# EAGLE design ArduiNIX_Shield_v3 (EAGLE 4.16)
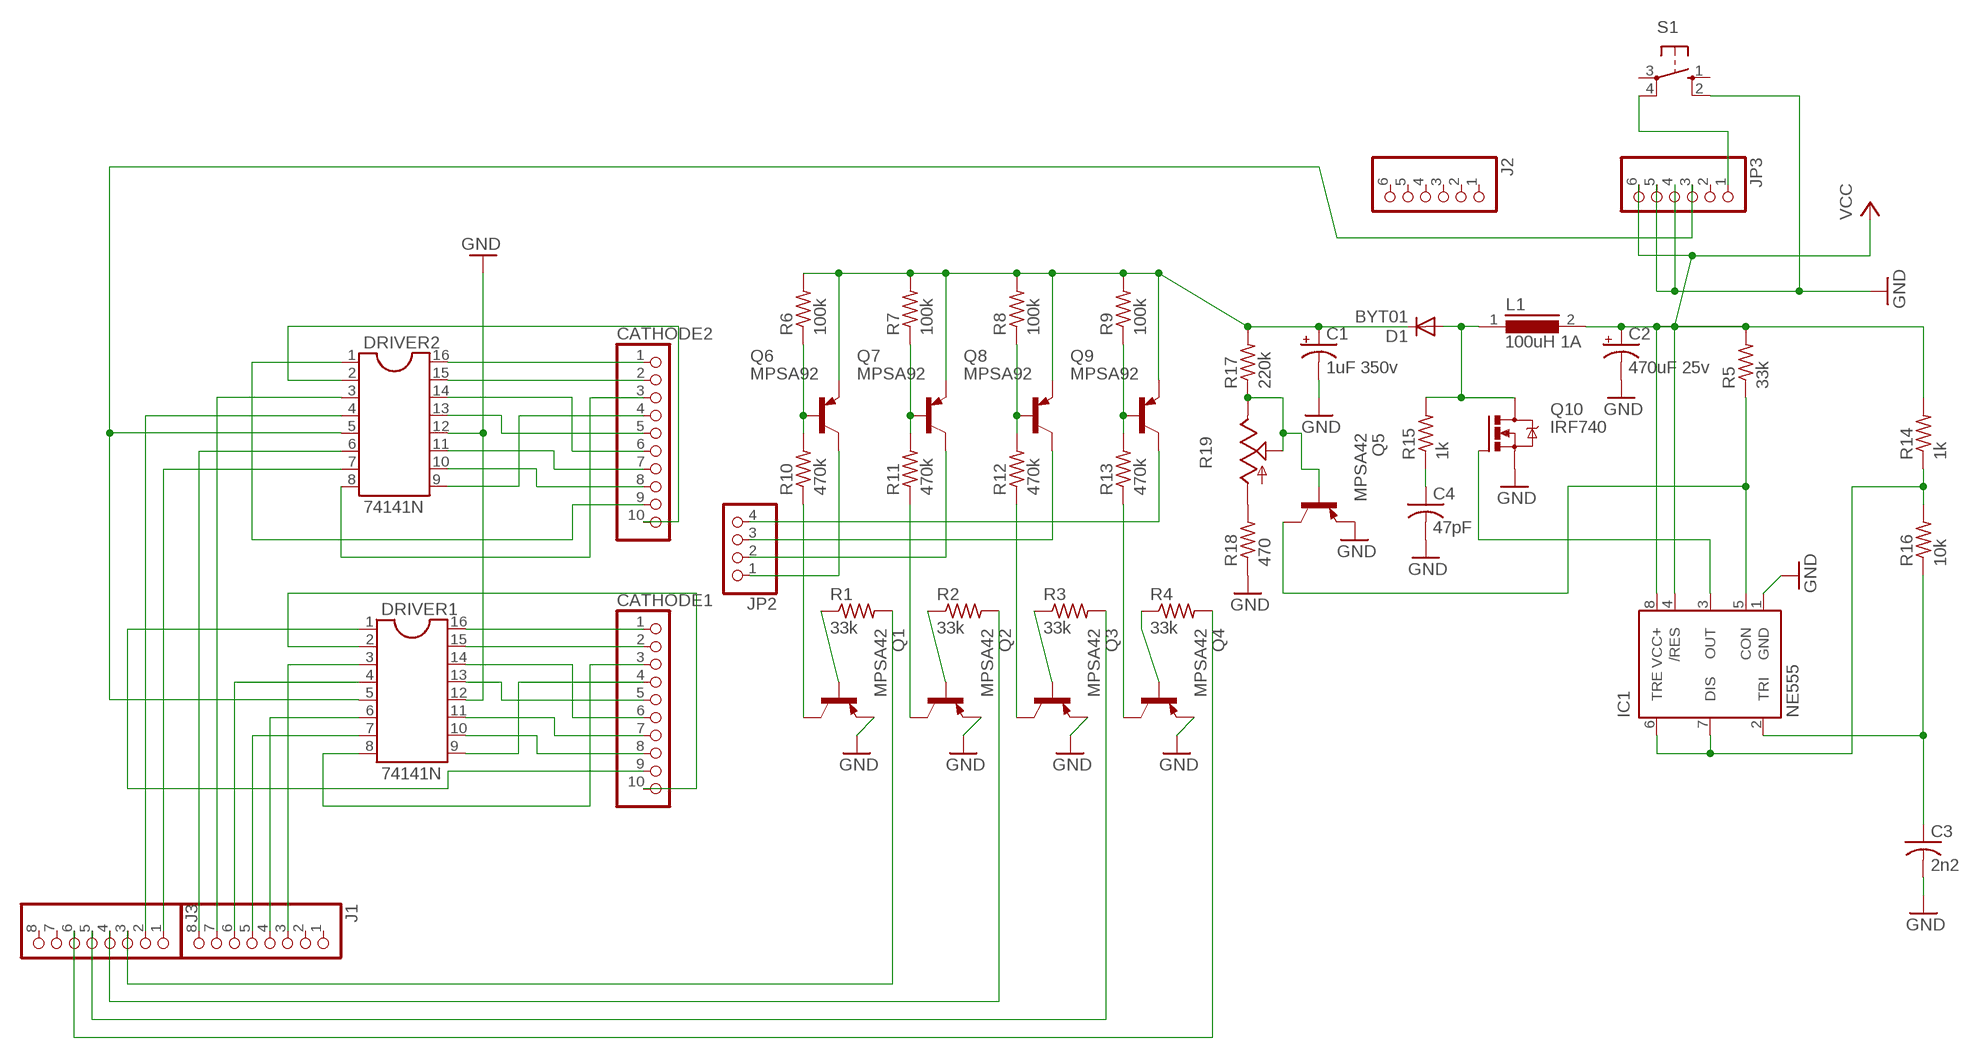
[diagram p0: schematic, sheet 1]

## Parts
C1  1uF 350v  CPOL-USE2.5-7  [E2,5-7]
C2  470uF 25v  CPOL-USE5-10.5  [E5-10,5]
C3  2n2  C-US050-024X044  [C050-024X044]
C4  47pF  C-US075-032X103  [C075-032X103]
CATHODE1  PINHD-1X10  [1X10]
CATHODE2  PINHD-1X10  [1X10]
D1  BYT01  [F126-10]
DRIVER1  74141N  DIL16  [DIL16]
DRIVER2  74141N  DIL16  [DIL16]
IC1  NE555  [DIL-08]
J1  PINHD-1X8  [1X08]
J2  PINHD-1X6  [1X06]
J3  PINHD-1X8  [1X08]
JP2  PINHD-1X4  [1X04]
JP3  PINHD-1X6  [1X06]
L1  100uH 1A  MESC26  [MESC26]
Q1  MPSA42  2N4126  [TO92-CBE]
Q2  MPSA42  2N4126  [TO92-CBE]
Q3  MPSA42  2N4126  [TO92-CBE]
Q4  MPSA42  2N4126  [TO92-CBE]
Q5  MPSA42  2N4126  [TO92-CBE]
Q6  MPSA92  2N4126  [TO92-CBE]
Q7  MPSA92  2N4126  [TO92-CBE]
Q8  MPSA92  2N4126  [TO92-CBE]
Q9  MPSA92  2N4126  [TO92-CBE]
Q10  IRF740  [TO220BV]
R1  33k  R-US_0207/2V  [0207/2V]
R2  33k  R-US_0207/2V  [0207/2V]
R3  33k  R-US_0207/2V  [0207/2V]
R4  33k  R-US_0207/2V  [0207/2V]
R5  33k  R-US_0207/2V  [0207/2V]
R6  100k  R-US_0207/2V  [0207/2V]
R7  100k  R-US_0207/2V  [0207/2V]
R8  100k  R-US_0207/2V  [0207/2V]
R9  100k  R-US_0207/2V  [0207/2V]
R10  470k  R-US_0207/2V  [0207/2V]
R11  470k  R-US_0207/2V  [0207/2V]
R12  470k  R-US_0207/2V  [0207/2V]
R13  470k  R-US_0207/2V  [0207/2V]
R14  1k  R-US_0207/2V  [0207/2V]
R15  1k  R-US_0207/2V  [0207/2V]
R16  10k  R-US_0207/2V  [0207/2V]
R17  220k  R-US_0207/2V  [0207/2V]
R18  470  R-US_0207/2V  [0207/2V]
R19  TRIM_US-B25P  [B25P]
S1  10-XX  [B3F-10XX]

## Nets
5V: DRIVER1.5 DRIVER2.5 JP3.3
GND: C1.- C2.- C3.2 C4.2 DRIVER1.12 DRIVER2.12 IC1.1(GND) JP3.4 JP3.5 Q1.E Q2.E Q3.E Q4.E Q5.E Q10.S R18.1 S1.2(S1)
N$1: CATHODE2.2 DRIVER2.15
N$2: Q6.B R6.1 R10.2
N$3: CATHODE2.3 DRIVER2.8
N$4: DRIVER1.3 J1.3
N$5: DRIVER1.6 J1.4
N$6: DRIVER1.7 J1.5
N$7: CATHODE1.10 DRIVER1.2
N$8: C4.1 R15.1
N$9: DRIVER2.6 J1.8
N$10: DRIVER2.7 J3.1
N$11: DRIVER2.3 J1.7
N$12: CATHODE2.4 DRIVER2.9
N$13: CATHODE2.5 DRIVER2.13
N$14: CATHODE2.6 DRIVER2.14
N$15: CATHODE2.7 DRIVER2.11
N$16: CATHODE2.8 DRIVER2.10
N$17: CATHODE2.9 DRIVER2.1
N$18: CATHODE2.10 DRIVER2.2
N$19: C1.+ D1.C Q6.E Q7.E Q8.E Q9.E R6.2 R7.2 R8.2 R9.2 R17.2
N$20: CATHODE1.2 DRIVER1.15
N$21: CATHODE1.6 DRIVER1.14
N$22: CATHODE2.1 DRIVER2.16
N$23: DRIVER2.4 J3.2
N$24: DRIVER1.4 J1.6
N$25: CATHODE1.4 DRIVER1.9
N$26: CATHODE1.8 DRIVER1.10
N$27: CATHODE1.7 DRIVER1.11
N$28: CATHODE1.5 DRIVER1.13
N$29: CATHODE1.9 DRIVER1.1
N$30: Q1.B R1.1
N$31: Q2.B R2.1
N$32: Q3.B R3.1
N$33: J3.3 R1.2
N$34: J3.4 R2.2
N$35: J3.5 R3.2
N$36: Q1.C R10.1
N$37: Q2.C R11.1
N$38: Q3.C R12.1
N$39: JP2.1 Q6.C
N$40: JP2.2 Q7.C
N$41: JP2.3 Q8.C
N$42: Q7.B R7.1 R11.2
N$43: Q8.B R8.1 R12.2
N$44: CATHODE1.3 DRIVER1.8
N$45: D1.A L1.1 Q10.D R15.2
N$46: Q5.B R17.1 R19.E R19.S
N$47: R18.2 R19.A
N$49: Q9.B R9.1 R13.2
N$50: IC1.6(TRE) IC1.7(DIS) R14.1 R16.2
N$51: JP2.4 Q9.C
N$52: JP3.1 S1.4(P1)
N$53: IC1.3(OUT) Q10.G
N$54: IC1.5(CON) Q5.C R5.1
N$56: C3.1 IC1.2(TRI) R16.1
N$58: Q4.C R13.1
N$59: Q4.B R4.1
N$60: J3.6 R4.2
N$61: CATHODE1.1 DRIVER1.16
VCC: C2.+ IC1.4(/RES) IC1.8(VCC+) JP3.6 L1.2 R5.2 R14.2
Unconnected: J1.1 J1.2 J2.1 J2.2 J2.3 J2.4 J2.5 J2.6 J3.7 J3.8 JP3.2 S1.1(S) S1.3(P)

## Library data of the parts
C1 C2 = rcl:CPOL-US: POLARIZED CAPACITOR, American symbol
C3 C4 = rcl:C-US: CAPACITOR, American symbol
CATHODE1 CATHODE2 = pinhead:PINHD-1X10: PIN HEADER
D1 = diode:BYT01: DIODE
DRIVER1 DRIVER2 = ic-package:DIL16: Dual In Line
IC1 = st-microelectronics:NE555: General purpose bipolar Timer
J1 J3 = pinhead:PINHD-1X8: PIN HEADER
J2 JP3 = pinhead:PINHD-1X6: PIN HEADER
JP2 = pinhead:PINHD-1X4: PIN HEADER
L1 = inductors:MESC26: INDUCTOR
Q1-Q9 = transistor-pnp:2N4126*: PNP Transistror
Q10 = transistor-power:IRF740: N-CHANNEL MOS FET
R1-R18 = rcl:R-US_: RESISTOR, American symbol
R19 = pot:TRIM_US-: POTENTIOMETER
S1 = switch-omron:10-XX: OMRON SWITCH

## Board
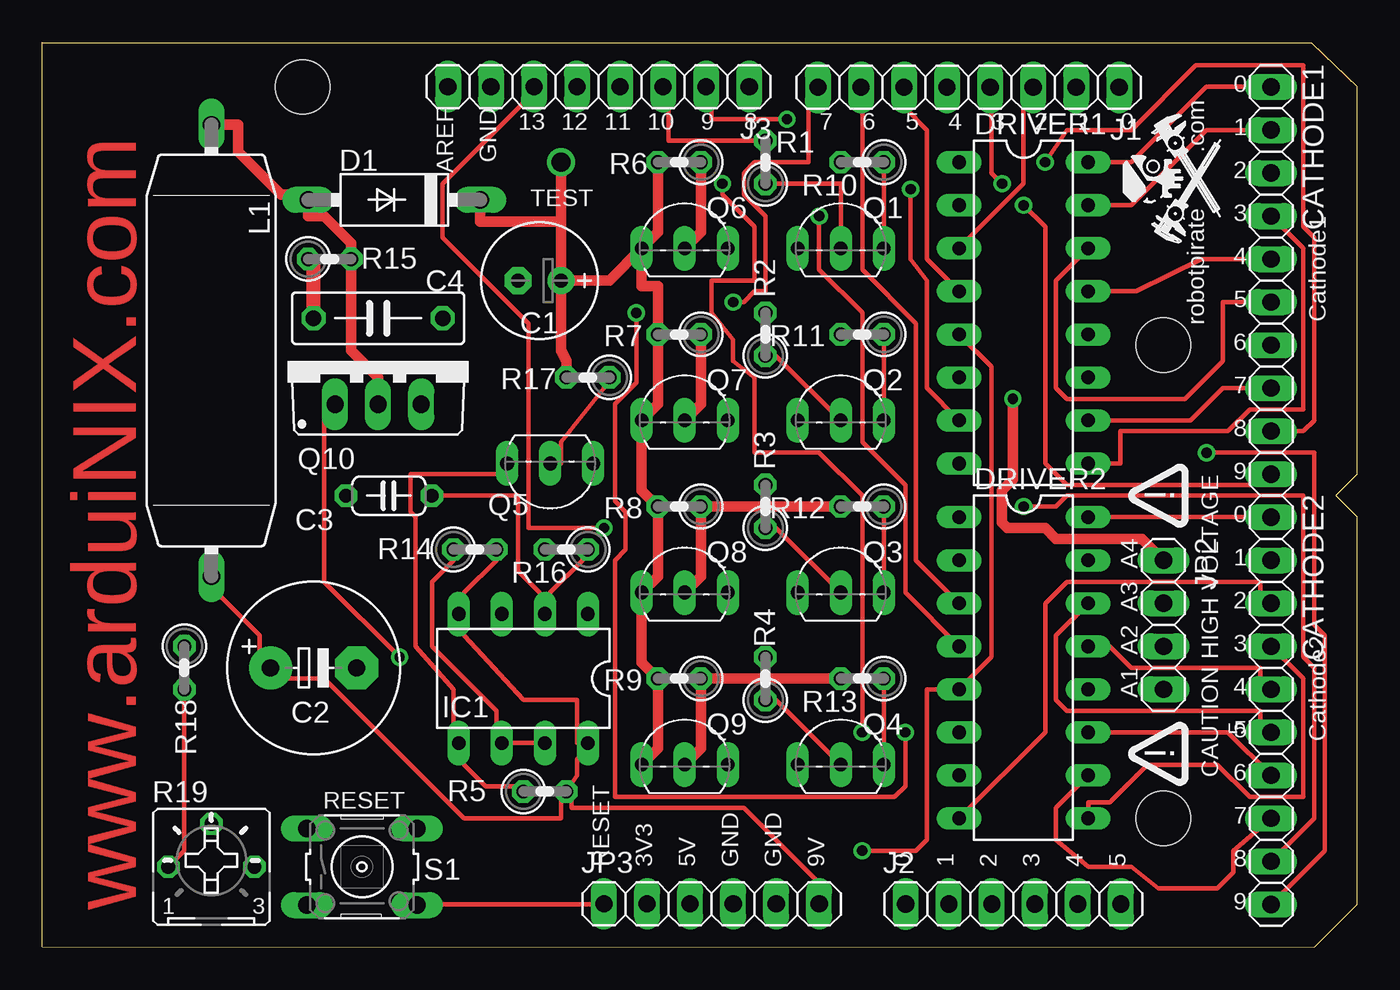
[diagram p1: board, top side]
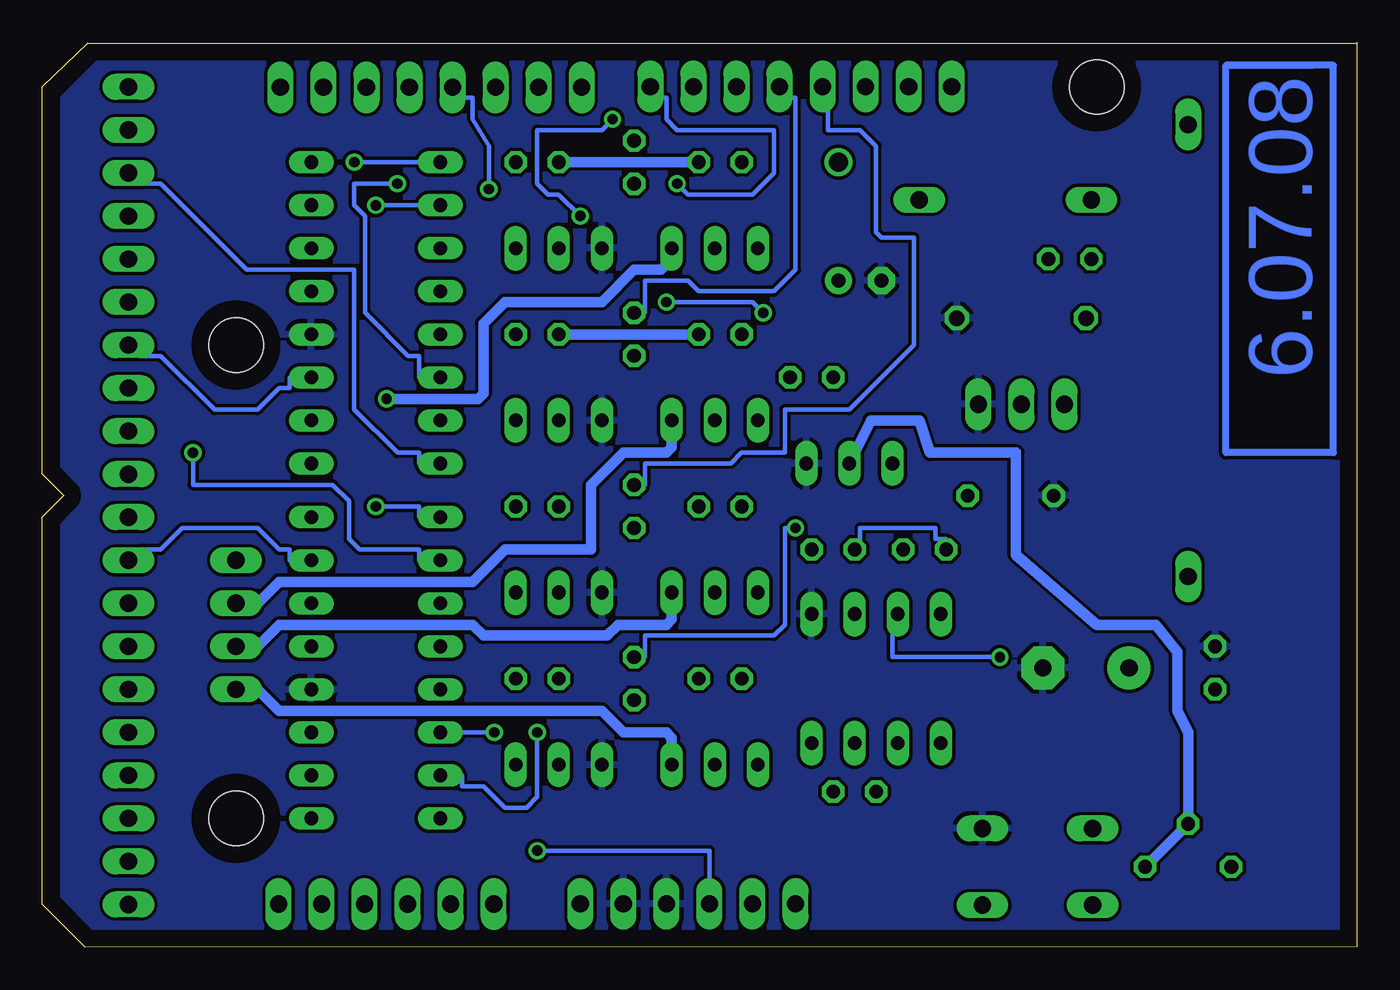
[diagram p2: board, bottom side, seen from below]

Size 77.6 x 53.43 mm. Coordinates in mm from the lower left corner, seen from the top.
Outline: 0,53.39 74.92,53.39 77.6,50.81 77.6,27.94 76.33,26.67 77.6,25.4 77.6,2.54 75.06,0 0,0.04 0,53.39
Outline: 0,53.39 0,53.43
Copper layers (1*16): Top 0.035mm / dielectric 1.5mm / Bottom 0.035mm
Design rules "default": minimum track width 10mil, minimum drill 24mil, track to track 8mil, track to pad 8mil, pad to pad 8mil, via to via 8mil, smd to smd 8mil, copper to edge 40mil, drill to drill 8mil, minimum pad ring 10mil, minimum via ring 8mil, stop-mask expansion 4mil, vias tented up to drill 0mil, thermal gap 10mil
Holes 3.2 mm at 15.37,50.8 66.17,35.56 66.17,7.62

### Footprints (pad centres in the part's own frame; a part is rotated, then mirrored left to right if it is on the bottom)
E2,5-7 = drill 0.813 pad 1.6 round: + -1.27,0 | drill 0.813 pad 1.6 octagon: - 1.27,0
E5-10,5 = drill 1.016 pad 2.54 round: + -2.54,0 | drill 1.016 pad 2.54 octagon: - 2.54,0
C050-024X044 = drill 0.813 octagon: 1 -2.54,0; 2 2.54,0
C075-032X103 = drill 0.914 octagon: 1 -3.81,0; 2 3.81,0
1X10 = drill 1.016 long: 1 -11.43,0; 2 -8.89,0; 3 -6.35,0; 4 -3.81,0; 5 -1.27,0; 6 1.27,0; 7 3.81,0; 8 6.35,0; 9 8.89,0; 10 11.43,0
F126-10 = drill 1.016 long: A 5.08,0; C -5.08,0
DIL16 = drill 0.813 long: 1 -8.89,-3.81; 2 -6.35,-3.81; 3 -3.81,-3.81; 4 -1.27,-3.81; 5 1.27,-3.81; 6 3.81,-3.81; 7 6.35,-3.81; 8 8.89,-3.81; 9 8.89,3.81; 10 6.35,3.81; 11 3.81,3.81; 12 1.27,3.81; 13 -1.27,3.81; 14 -3.81,3.81; 15 -6.35,3.81; 16 -8.89,3.81
DIL-08 = drill 0.813 long: 1 -3.81,-3.81; 2 -1.27,-3.81; 3 1.27,-3.81; 4 3.81,-3.81; 5 3.81,3.81; 6 1.27,3.81; 7 -1.27,3.81; 8 -3.81,3.81
1X08 = drill 1.016 long: 1 -8.89,0; 2 -6.35,0; 3 -3.81,0; 4 -1.27,0; 5 1.27,0; 6 3.81,0; 7 6.35,0; 8 8.89,0
1X06 = drill 1.016 long: 1 -6.35,0; 2 -3.81,0; 3 -1.27,0; 4 1.27,0; 5 3.81,0; 6 6.35,0
1X04 = drill 1.016 long: 1 -3.81,0; 2 -1.27,0; 3 1.27,0; 4 3.81,0
MESC26 = drill 1.016 long: 1 -13.335,0; 2 13.335,0
TO92-CBE = drill 0.813 long: B 0,0; C 2.54,0; E -2.54,0
TO220BV = drill 1.016 long: D 0,-2.54; G -2.54,-2.54; S 2.54,-2.54
0207/2V = drill 0.813 octagon: 1 -1.27,0; 2 1.27,0
B25P = drill 0.813 octagon: A -2.54,0; E 2.54,0; S 0,2.54
B3F-10XX = drill 1.016 long: 1 -3.251,2.261; 2 3.251,2.261; 3 -3.251,-2.261; 4 3.251,-2.261

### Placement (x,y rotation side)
C1  29.34,39.37 180 top
C2  16,16.51 0 top
C3  20.45,26.67 180 top
C4  19.81,37.15 0 top
CATHODE1  72.52,39.37 270 top
CATHODE2  72.52,13.97 270 top
D1  20.77,44.13 180 top
DRIVER1  57.91,37.47 270 top
DRIVER2  57.91,16.51 270 top
IC1  28.39,15.88 180 top
J1  54.67,50.78 180 top
J2  57.31,2.57 0 top
J3  32.83,50.82 180 top
JP2  66.17,19.05 270 top
JP3  39.5,2.58 0 top
L1  9.97,35.24 270 top
Q1  47.12,41.27 0 top
Q2  47.12,31.11 0 top
Q3  47.12,20.95 0 top
Q4  47.12,10.79 0 top
Q5  29.97,28.57 180 top
Q6  37.91,41.27 0 top
Q7  37.91,31.11 0 top
Q8  37.91,20.95 0 top
Q9  37.91,10.79 0 top
Q10  19.81,34.61 0 top
R1  42.68,46.35 90 top
R2  42.68,36.2 90 top
R3  42.68,26.04 90 top
R4  42.68,15.88 90 top
R5  29.66,9.21 0 top
R6  37.6,46.35 180 top
R7  37.6,36.2 180 top
R8  37.6,26.04 180 top
R9  37.6,15.88 180 top
R10  48.39,46.35 180 top
R11  48.39,36.2 180 top
R12  48.39,26.04 180 top
R13  48.39,15.88 180 top
R14  25.53,23.5 0 top
R15  16.96,40.64 0 top
R16  30.93,23.5 180 top
R17  32.2,33.66 180 top
R18  8.39,16.51 270 top
R19  9.97,4.76 0 top
S1  18.86,4.76 0 top
U$2  [TEST]  67.44,45.4 90 top

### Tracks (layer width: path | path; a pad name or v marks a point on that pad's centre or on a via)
5V  (via drill 0.61)
  Top 0.254: DRIVER1.5 56.01,34.29 56.01,17.14 DRIVER2.5 52.2,15.24 52.2,6.35 51.57,5.71 v48.39,5.71
  Bottom 0.254: v48.39,5.71 38.23,5.71 JP3.3
GND
  pour Bottom: 76.33,50.16 73.79,52.7 0.77,52.7 0.77,0.64 74.11,0.64 76.33,2.54 76.33,25.08 75.69,26.67 76.33,28.26
N$1
  Bottom 0.254: DRIVER2.15 63,22.86 63,23.5 63.63,23.5 64.9,24.77 69.34,24.77 70.61,23.5 71.88,23.5 CATHODE2.2
N$2
  Top 0.61: R6.1 38.87,42.23 Q6.B
  Bottom 0.61: R6.1 R10.2
N$3
  Top 0.254: DRIVER2.8 59.19,12.7 59.19,20.32 60.46,21.59 71.88,21.59 71.88,20.95 CATHODE2.3
N$4
  Top 0.254: DRIVER1.3 57.91,45.09 57.91,49.53 J1.3
N$5  (via drill 0.61)
  Top 0.254: v56.65,45.09 56.01,45.72 56.01,49.53 J1.4
  Bottom 0.254: v56.65,45.09 59.19,45.09 59.19,43.81 58.55,43.18 58.55,37.47 56.01,34.92 55.38,34.92 55.38,33.66 DRIVER1.6
N$6  (via drill 0.61)
  Top 0.254: v51.25,44.77 51.25,40.64 52.2,39.37 52.2,33.02 DRIVER1.7
  Bottom 0.254: v51.25,44.77 51.25,47.31 52.2,48.9 52.2,50.16 52.84,50.16 J1.5
N$7  (via drill 0.61)
  Top 0.254: v57.91,43.81 59.19,42.55 59.19,28.57 60.46,27.3 71.25,27.3 71.25,27.94 CATHODE1.10
  Bottom 0.254: v57.91,43.81 DRIVER1.2
N$8
  Top 0.254: 16,40.64 R15.1
  Top 0.813: C4.1 16,40.64
N$9  (via drill 0.61)
  Top 0.254: v50.93,12.7 50.93,9.53 50.3,8.89 33.79,8.89 33.79,22.86 34.42,23.5 34.42,25.72 33.79,26.35 33.79,32.07 35.05,33.34 v35.05,37.47 | v40.77,38.1 41.41,38.1 42.04,38.73 42.68,38.73 42.68,43.18 41.41,44.45 41.41,45.72 42.04,46.35 45.22,46.35 45.22,49.53 J1.8
  Bottom 0.254: v35.05,37.47 35.69,38.1 v40.77,38.1 | v50.93,12.7 DRIVER2.6
N$10  (via drill 0.61)
  Top 0.254: v48.39,12.7 48.39,26.67 45.85,29.21 42.04,29.21 42.04,33.66 40.77,34.61 40.77,35.88 39.5,37.47 39.5,39.37 42.04,39.37 42.04,42.55 40.14,44.45 v40.14,45.09
  Bottom 0.254: v48.39,12.7 48.39,8.89 49.03,8.26 50.3,8.26 51.57,9.53 52.84,9.53 52.84,10.16 DRIVER2.7 | v40.14,45.09 39.5,44.45 35.69,44.45 34.42,45.72 34.42,48.26 40.14,48.26 40.77,48.9 40.77,50.16 41.41,50.16 J3.1
N$11
  Top 0.254: DRIVER2.3 51.57,22.86 51.57,36.83 48.39,40.01 48.39,49.53 J1.7
N$12
  Top 0.254: DRIVER2.9 61.73,8.57 63,8.57 65.22,10.79 69.34,10.79 71.25,8.89 74.42,8.89 74.42,15.88 CATHODE2.4
N$13
  Top 0.254: DRIVER2.13 63,17.78 64.27,16.51 71.88,16.51 71.88,15.88 CATHODE2.5
N$14
  Top 0.254: DRIVER2.14 59.82,18.41 59.82,14.61 60.46,13.97 71.88,13.97 71.88,13.34 CATHODE2.6
N$15
  Top 0.254: DRIVER2.11 69.98,12.7 CATHODE2.7
N$16
  Top 0.254: DRIVER2.10 59.82,8.26 59.82,6.35 61.73,4.76 64.27,4.76 65.85,3.49 69.34,3.49 70.3,4.45 70.3,5.71 CATHODE2.8
N$17  (via drill 0.61)
  Top 0.254: v57.91,26.04 59.82,26.04 60.46,26.67 74.42,26.67 74.42,17.14 75.06,16.51 75.06,7.62 CATHODE2.9
  Bottom 0.254: v57.91,26.04 55.38,26.04 55.38,25.4 DRIVER2.1
N$18  (via drill 0.61)
  Top 0.254: v68.71,29.21 75.06,29.21 75.06,19.05 75.69,18.41 75.69,5.71 CATHODE2.10
  Bottom 0.254: v68.71,29.21 68.71,27.3 60.46,27.3 59.5,26.35 59.5,24.13 58.87,23.5 55.38,23.5 55.38,22.86 DRIVER2.2
N$19  (via drill 1.1)
  Top 0.254: R17.2 30.61,33.66
  Top 0.61: D1.C 25.85,42.86 30.61,42.86 | C1.+ 30.61,42.86 | C1.+ 33.47,39.37 Q6.E | R6.2 36.33,42.23 Q6.E | Q6.E 35.37,39.05 36.33,39.05 R7.2 36.33,32.07 Q7.E 35.37,26.99 R8.2 36.33,21.91 Q8.E 35.37,16.83 R9.2 36.33,11.75 Q9.E | C1.+ 30.61,35.24 30.93,34.61 R17.2 | 30.61,42.86 v30.61,46.35
N$20
  Top 0.254: DRIVER1.15 64.27,43.81 68.71,48.26 CATHODE1.2
N$21
  Top 0.254: DRIVER1.14 59.82,39.37 59.82,33.02 60.46,32.38 67.44,32.38 69.66,34.61 69.66,38.1 CATHODE1.6
N$22
  Top 0.254: DRIVER2.16 CATHODE2.1
N$23  (via drill 0.61)
  Top 0.254: v45.85,43.18 45.85,40.01 48.39,37.47 48.39,29.84 50.93,27.3 50.93,20.95 DRIVER2.4 | v43.95,48.9 39.5,48.9 39.5,49.53 J3.2
  Bottom 0.254: v45.85,43.18 47.12,44.45 47.76,44.45 48.39,45.09 48.39,48.26 44.58,48.26 v43.95,48.9
N$24
  Top 0.254: DRIVER1.4 52.2,40.64 52.2,48.26 50.93,49.53 J1.6
N$25
  Top 0.254: DRIVER1.9 63.63,28.57 63.63,30.48 69.98,30.48 71.25,31.75 74.42,31.75 74.42,41.27 CATHODE1.4
N$26
  Top 0.254: DRIVER1.10 67.76,31.11 69.66,33.02 CATHODE1.8
N$27
  Bottom 0.254: DRIVER1.11 63,33.66 63,33.02 63.63,33.02 64.9,31.75 67.44,31.75 70.61,34.92 71.88,34.92 CATHODE1.7
N$28
  Top 0.254: DRIVER1.13 64.58,38.73 68.39,40.64 CATHODE1.5
N$29  (via drill 0.61)
  Top 0.254: v59.19,46.35 60.46,48.26 64.27,48.26 68.07,52.07 74.42,52.07 74.42,42.55 75.06,41.91 75.06,31.11 74.42,30.48 CATHODE1.9
  Bottom 0.254: DRIVER1.1 v59.19,46.35
N$30
  Top 0.254: R1.1 47.12,45.09 Q1.B
N$31
  Top 0.254: R2.1 43.31,34.92 Q2.B
N$32
  Top 0.254: R3.1 43.31,24.77 Q3.B
N$33
  Top 0.254: R1.2 36.96,47.62 36.96,49.53 J3.3
N$34
  Bottom 0.254: R2.2 42.04,37.47 42.04,39.37 39.5,39.37 38.87,38.73 34.42,38.73 33.15,40.01 33.15,50.16 33.79,50.16 J3.4
N$35
  Bottom 0.254: R3.2 42.04,27.3 42.04,28.57 36.96,28.57 36.33,29.21 33.79,29.21 33.79,31.75 29.97,31.75 26.16,35.56 26.16,41.91 28.07,41.91 28.39,42.23 28.39,47.31 29.34,48.26 31.24,48.26 31.24,49.53 J3.5
N$36
  Top 0.254: Q1.C R10.1
N$37
  Top 0.254: Q2.C R11.1
N$38
  Top 0.254: Q3.C R12.1
N$39  (via drill 0.61)
  Top 0.61: v57.28,32.38 57.28,27.62 56.65,26.99 56.65,25.08 56.96,24.77 59.19,24.77 59.82,24.13 64.9,24.13 JP2.1
  Bottom 0.61: Q6.C 40.45,40.64 41.09,40.01 42.68,40.01 44.58,38.1 50.3,38.1 51.57,36.83 51.57,32.7 51.88,32.38 v57.28,32.38
N$40
  Bottom 0.61: Q7.C 40.45,29.53 40.77,29.21 43.31,29.21 45.22,27.3 45.22,23.5 50.3,23.5 52.2,21.59 63.63,21.59 64.9,20.32 JP2.2
N$41
  Bottom 0.61: Q8.C 40.45,19.37 40.77,19.05 43.63,19.05 44.26,18.41 51.57,18.41 52.2,19.05 63.63,19.05 64.9,17.78 JP2.3
N$42
  Top 0.61: R7.1 38.87,32.07 Q7.B
  Bottom 0.61: R7.1 R11.2
N$43
  Top 0.61: Q8.B 38.87,21.91 R8.1 R12.2
N$44
  Bottom 0.254: DRIVER1.8 55.38,28.57 55.38,29.21 56.65,29.21 59.19,31.75 59.19,40.01 65.53,40.01 70.61,45.09 71.88,45.09 CATHODE1.3
N$45
  Top 0.61: L1.1 11.56,48.58 11.56,46.99 14.1,44.45 15.37,44.45 D1.A 15.69,43.18 16.64,43.18 18.23,41.59 18.23,40.96 17.91,40.64 R15.2 18.23,35.24 19.81,33.66 Q10.D
N$46
  Top 0.254: R17.1 33.15,33.66 33.15,33.02 30.61,29.84 30.61,28.57 Q5.B
  Bottom 0.61: Q5.B 28.7,31.11 25.85,31.11 25.21,29.21 20.13,29.21 20.13,23.18 15.37,19.05 11.88,19.05 10.61,17.46 10.61,13.97 9.97,12.7 R19.S R19.E
N$47
  Top 0.254: R19.A 8.39,5.71 R18.2
N$49
  Top 0.61: Q9.B 38.87,11.75 R9.1 R13.2
N$50
  Top 0.254: IC1.7 IC1.6 26.8,13.34 26.8,13.97 22.99,17.78 22.99,21.59 24.26,22.86 R14.1
  Bottom 0.254: R16.2 29.34,23.5 29.34,24.77 24.89,24.77 24.89,24.13 24.26,24.13 R14.1
N$51
  Bottom 0.61: Q9.C 40.45,12.38 40.77,12.7 43.31,12.7 44.58,13.97 63.63,13.97 64.9,15.24 JP2.4
N$52
  Top 0.254: S1.4 23.62,2.54 32.52,2.54 JP3.1
N$53  (via drill 0.61)
  Top 0.254: v21.08,17.14 16.64,21.59 16.64,31.11 Q10.G
  Bottom 0.254: v21.08,17.14 27.43,17.14 27.43,18.41 IC1.3
N$54
  Top 0.254: R5.1 28.07,9.53 26.16,9.53 24.89,10.79 IC1.5 24.26,13.34 24.26,15.24 22.04,17.78 22.04,25.4 21.72,25.72 21.72,27.94 26.8,27.94 Q5.C
N$56
  Top 0.254: R16.1 31.88,23.5 31.88,22.86 29.97,20.95 IC1.2 29.34,20.95 28.07,22.23 28.07,26.67 C3.1
N$58
  Top 0.254: Q4.C R13.1
N$59
  Top 0.254: R4.1 43.31,14.61 Q4.B
N$60  (via drill 0.61)
  Top 0.254: v33.15,24.77 28.7,24.77 28.7,36.83 23.62,41.91 23.62,45.09 28.7,50.16 J3.6
  Bottom 0.254: v33.15,24.77 33.79,24.77 33.79,19.05 34.42,18.41 42.04,18.41 42.04,17.14 R4.2
N$61
  Top 0.254: DRIVER1.16 64.27,46.35 68.71,50.8 CATHODE1.1
N$62
  Bottom 0.406: 7.75,52.07 2.67,52.07 | 7.75,52.07 7.75,29.21 1.4,29.21 1.4,52.07 7.75,52.07
VCC
  Top 0.254: L1.2 10.29,20.95 12.83,18.41 12.83,17.14 C2.+ 14.1,15.88 16.64,15.88 24.89,7.62 30.61,7.62 30.61,8.89 R5.2 | R14.2 26.8,22.86 24.89,20.95 IC1.4 24.89,18.41 28.39,14.61 31.56,14.61 31.56,12.06 IC1.8 31.56,11.11 31.56,10.16 R5.2 | JP3.6 45.85,3.81 41.41,8.26 31.24,8.26 31.24,8.89 R5.2

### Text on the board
Top: www.arduiNIX.com
Bottom: 6.07.08
tPlace: ! | !
tNames: 0 | 13 | 12 | 11 | 10 | 9 | 8 | 7 | 6 | 5 | 4 | 3 | 2 | 1 | 0 | 1 | AREF | GND | TEST | 2 | 3 | Cathode1 | 4 | 5 | 6 | 7 | 8 | CAUTION HIGH VOLTAGE | 9 | 0 | A4 | 1 | A3 | 2 | A2 | Cathode2 | A1 | 3 | 4 | 5 | 5 | 6 | RESET | 7 | RESET | 3V3 | 5V | GND | GND | 9V | 0 | 1 | 2 | 3 | 4 | 5 | 8 | 9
